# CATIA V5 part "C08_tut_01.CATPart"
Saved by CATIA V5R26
Part number: Part1
Bounding box of the stored display mesh (mm): x -175 to 175, y -250 to 250, z -8 to 100
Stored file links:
  D:\_Deepak\CATIA\CATIA V5 2015 Parts Files\Tutorial Files\Tutorials\c08_catia_v5_6r2015_tut\C08_tut_01.CATPart
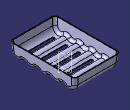
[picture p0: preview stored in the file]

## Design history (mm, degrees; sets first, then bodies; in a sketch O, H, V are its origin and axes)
Body1 (main body)
  Sketch1 on yz-plane, origin (0, 0, 0), H (0, 1, 0), V (0, 0, 1)
    point P1 (-250, 0)
    line L1 (-250, 0) -> (250, 0)
    line L2 (250, 0) -> (250, 100)
    line L3 (250, 100) -> (-250, 100)
    line L4 (-250, 100) -> (-250, 0)
    length L3 = 500
    length L2 = 100
    distance V L2 = 250
    coincidence: P1 H
    horizontal: L1 H, L3 H
    vertical: L2 V, L4 V
  Pad1: profile Sketch1, direction (1, 0, 0), length 175, mirrored extent
  Draft1: Angle -5, Neutral face of Pad1 from Sketch1.L3, PullDir face of Pad1 from Sketch1.L3
  Sketch2 on yz-plane, origin (0, 0, 0), H (0, 1, 0), V (0, 0, 1)
    arc A1 centre (-195.4346, 50) radius 50 from (-245.2443, 45.6422) to (-162.8621, 12.0654) ccw
    reference projected line E1 (-241.2511, 0) -> (-250, 100) from edge [end face of Pad1 | face of Pad1 from Sketch1.L4]
    reference projected line E2 (241.2511, 0) -> (-241.2511, 0) from edge [end face of Pad1 | face of Pad1 from Sketch1.L1]
    arc A2 centre (195.4346, 50) radius 50 from (162.8622, 12.0653) to (245.2443, 45.6422) ccw
    reference projected line E3 (250, 100) -> (241.2511, 0) from edge [end face of Pad1 | face of Pad1 from Sketch1.L2]
    reference projected line E4 (241.2511, 0) -> (-241.2511, 0) from edge [end face of Pad1 | face of Pad1 from Sketch1.L1]
    point P3 (97.7173, 50)
    point P4 (0, 50)
    point P5 (-97.7173, 50)
    construction line L1 (195.4346, 50) -> (-195.4346, 50)
    point P7 (-48.8586, -6.902)
    projected line E5 (250, 100) -> (241.2511, 0) from edge [end face of Pad1 | face of Pad1 from Sketch1.L2]
    projected line E6 (-241.2511, 0) -> (-250, 100) from edge [end face of Pad1 | face of Pad1 from Sketch1.L4]
    arc A3 centre (97.7173, 50) radius 50 from (65.1449, 12.0653) to (130.2898, 12.0654) ccw
    arc A4 centre (0, 50) radius 50 from (-32.5724, 12.0653) to (32.5725, 12.0654) ccw
    arc A5 centre (-97.7173, 50) radius 50 from (-130.2897, 12.0653) to (-65.1448, 12.0654) ccw
    point P23 (-245.2443, 45.6422)
    arc A6 centre (-146.5759, -6.902) radius 25 from (-130.2897, 12.0653) to (-162.8621, 12.0654) ccw
    arc A7 centre (-48.8586, -6.902) radius 25 from (-32.5724, 12.0653) to (-65.1448, 12.0654) ccw
    arc A8 centre (48.8586, -6.902) radius 25 from (65.1449, 12.0653) to (32.5725, 12.0654) ccw
    arc A9 centre (146.5759, -6.902) radius 25 from (162.8622, 12.0653) to (130.2898, 12.0654) ccw
    axis line L2 (146.5759, -6.902) -> (-146.5759, -6.902)
    line L3 (245.2443, 45.6422) -> (237.7725, -39.761)
    line L4 (-245.2443, 45.6422) -> (-237.7725, -39.761)
    line L5 (-237.7725, -39.761) -> (237.7725, -39.761)
    radius A1 = 50
    radius A6 = 25
    radius A5 = 50
    radius A7 = 25
    radius A4 = 50
    radius A8 = 25
    radius A3 = 50
    radius A9 = 25
    tangency: A1 E1, A1 E2, A2 E3, A2 E4, A6 A5, A7 A5, A6 A1, A7 A4, A8 A4, A8 A3, A3 A9, A9 A2, L3 A2, L4 A1
    horizontal: L1 H, L2 H, L5 H
    coincidence: P3 L1, P4 L1, P5 L1, P4 V, E6 P23, L2 P7
  Pocket1: profile Sketch2, direction (-1, 0, 0), through (limit type 3), opposite side length 175
  Fillet1: radius 25, on edge [face of Pocket1 | end face of Pad1]; edge [start face of Pad1 | face of Pad1 from Sketch1.L2]
  Shell1: ExtOffset 0, Face face of Pad1 from Sketch1.L3, IntOffset 5
  Sketch3 on xy-plane, origin (0, 0, 0), H (1, 0, 0), V (0, 1, 0)
    point P1 (0, 195.4)
    line L1 (105, 183.4) -> (-105, 183.4)
    line L2 (-105, 207.4) -> (105, 207.4)
    arc A1 centre (105, 195.4) radius 12 from (105, 183.4) to (105, 207.4) ccw
    point P6 (105, 195.4)
    arc A2 centre (-105, 195.4) radius 12 from (-105, 207.4) to (-105, 183.4) ccw
    point P7 (-105, 195.4)
    point P8 (-105, 207.4)
    axis line L3 (105, 195.4) -> (-105, 195.4)
    reference projected line E1 (175, 250) -> (-175, 250) from edge [face of Pad1 from Sketch1.L2 | face of Pad1 from Sketch1.L3]
    distance P6 P7 = 210
    distance V P7 = 105
    distance L2 L1 = 24
    distance E1 L3 = 54.6
    coincidence: P1 V, A2 P8
    horizontal: L1 H, L2 H, L3 H
    equidistance: L1 L2 P1
    tangency: A1 L1, A2 L2, A1 L2, L1 A2
  Pocket2: profile Sketch3, direction (0, 0, -1), through (limit type 6), opposite side length 25
  RectPattern1: of Pocket2, direction 1 instances 5, spacing 97.7, along edge [end face of Pad1 | face of Pad1 from Sketch1.L3] reversed
  Sketch4 on xy-plane, origin (0, 0, 0), H (1, 0, 0), V (0, 1, 0)
    circle A1 centre (-135, -196) radius 10
    point P1 (-135, -196)
    reference projected line E1 (-175, 250) -> (-175, -250) from edge [start face of Pad1 | face of Pad1 from Sketch1.L3]
    reference projected line E2 (-175, -250) -> (175, -250) from edge [face of Pad1 from Sketch1.L4 | face of Pad1 from Sketch1.L3]
    radius A1 = 10
    distance E1 P1 = 40
    distance P1 E2 = 54
  Pad2: profile Sketch4, direction (0, 0, 1), up to the existing solid (limit type 2), opposite side length 8
  RectPattern2: of Pad2, direction 1 instances 2, spacing 390.8, along edge [start face of Pad1 | face of Pad1 from Sketch1.L3] reversed, direction 2 instances 2, spacing 270, along edge [face of Pad1 from Sketch1.L4 | face of Pad1 from Sketch1.L3]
